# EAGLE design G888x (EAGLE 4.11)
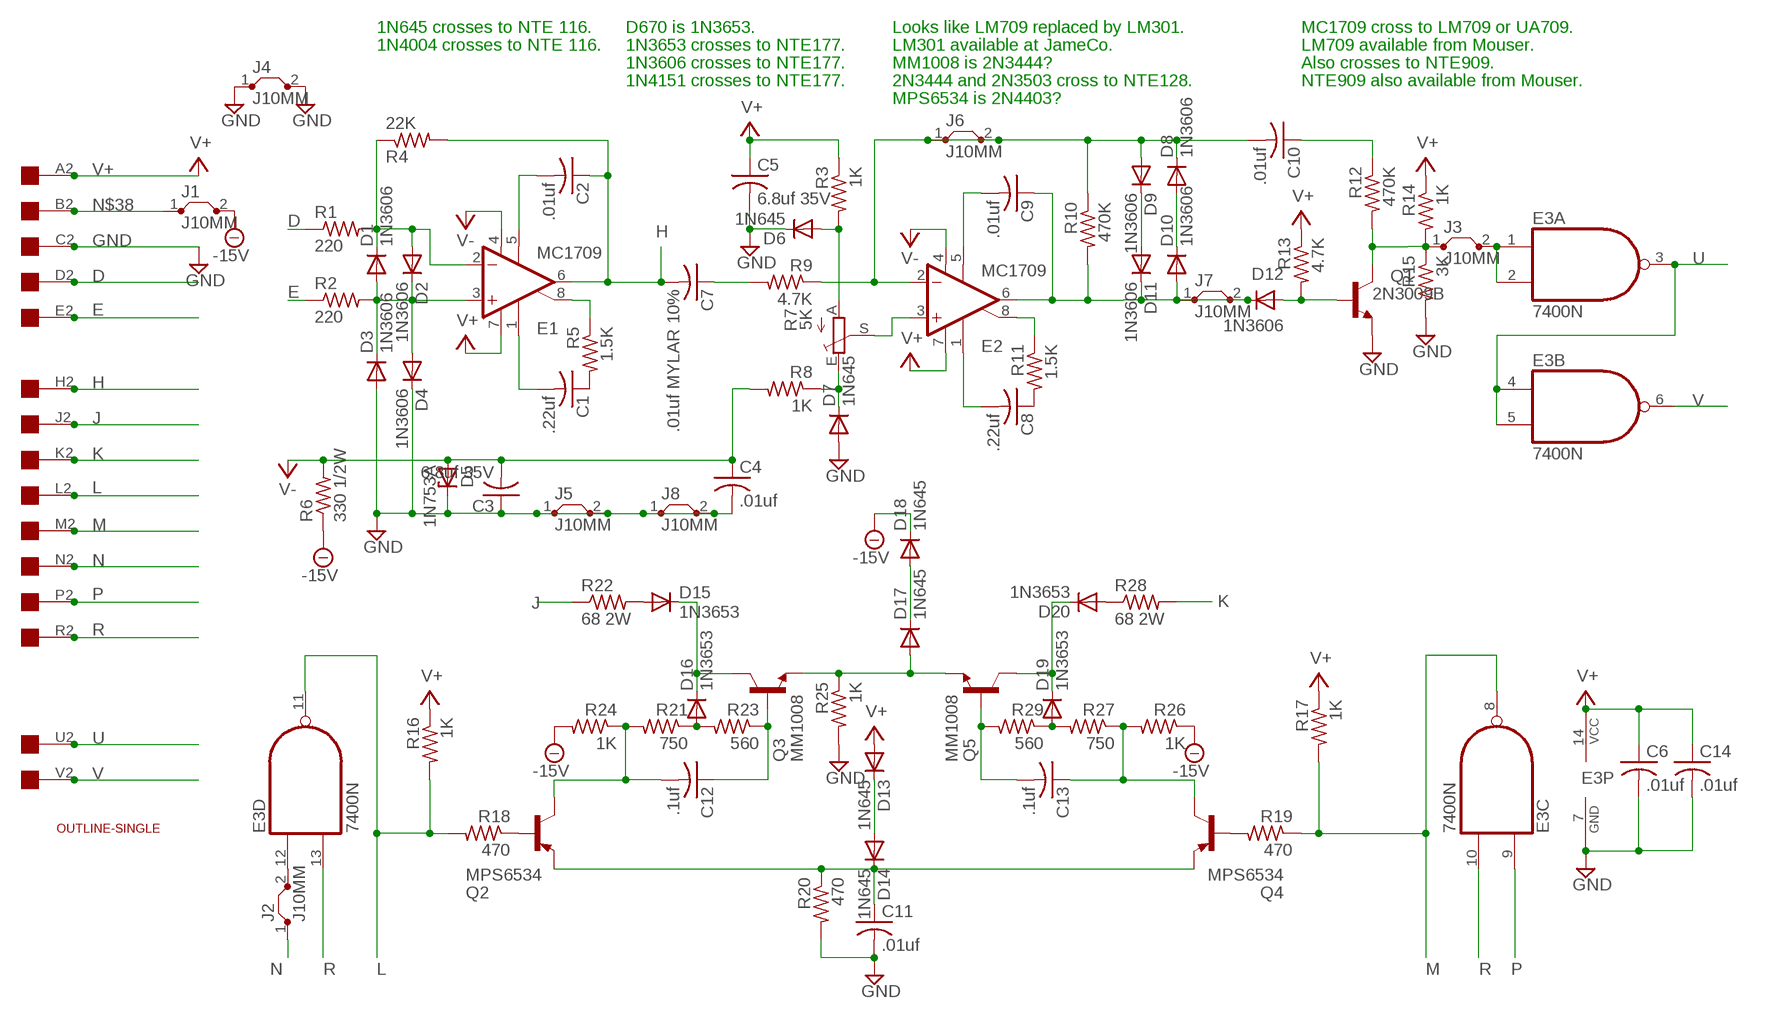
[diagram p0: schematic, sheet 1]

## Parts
C1  .22uf  C-US050-025X075  [C050-025X075]
C2  .01uf  C-US050-025X075  [C050-025X075]
C3  6.8uf 35V  C-US102-043X133  [C102-043X133]
C4  .01uf  C-US050-025X075  [C050-025X075]
C5  6.8uf 35V  C-US102-043X133  [C102-043X133]
C6  .01uf  C-US050-025X075  [C050-025X075]
C7  .01uf MYLAR 10%  C-US150-054X183  [C150-054X183]
C8  .22uf  C-US050-025X075  [C050-025X075]
C9  .01uf  C-US050-025X075  [C050-025X075]
C10  .01uf  C-US050-025X075  [C050-025X075]
C11  .01uf  C-US050-025X075  [C050-025X075]
C12  .1uf  C-US050-025X075  [C050-025X075]
C13  .1uf  C-US050-025X075  [C050-025X075]
C14  .01uf  C-US050-025X075  [C050-025X075]
D1  1N3606  1N4004  [DO41-10]
D2  1N3606  1N4004  [DO41-10]
D3  1N3606  1N4004  [DO41-10]
D4  1N3606  1N4004  [DO41-10]
D5  1N753A  ZENER-DIODEDO35Z10  [DO35Z10]
D6  1N645  1N4004  [DO41-10]
D7  1N645  1N4004  [DO41-10]
D8  1N3606  1N4004  [DO41-10]
D9  1N3606  1N4004  [DO41-10]
D10  1N3606  1N4004  [DO41-10]
D11  1N3606  1N4004  [DO41-10]
D12  1N3606  1N4004  [DO41-10]
D13  1N645  1N4004  [DO41-10]
D14  1N645  1N4004  [DO41-10]
D15  1N3653  1N4004  [DO41-10]
D16  1N3653  1N4004  [DO41-10]
D17  1N645  1N4004  [DO41-10]
D18  1N645  1N4004  [DO41-10]
D19  1N3653  1N4004  [DO41-10]
D20  1N3653  1N4004  [DO41-10]
E1  MC1709  LM3080N  [DIL08]
E2  MC1709  LM3080N  [DIL08]
E3  7400N  [DIL14]
J1  J10MM  [10]
J2  J10MM  [10]
J3  J10MM  [10]
J4  J10MM  [10]
J5  J10MM  [10]
J6  J10MM  [10]
J7  J10MM  [10]
J8  J10MM  [10]
Q1  2N3009B  2N1711  [TO39]
Q2  MPS6534  2N5415  [TO39]
Q3  MM1008  2N1711  [TO39]
Q4  MPS6534  2N5415  [TO39]
Q5  MM1008  2N1711  [TO39]
R1  220  R-US_0207/10  [0207/10]
R2  220  R-US_0207/10  [0207/10]
R3  1K  R-US_0207/10  [0207/10]
R4  22K  R-US_0207/10  [0207/10]
R5  1.5K  R-US_0207/10  [0207/10]
R6  330 1/2W  R-US_0411/15  [0411/15]
R7  5K  TRIM_EU-PTSPIN  [PT-SPIN]
R8  1K  R-US_0207/10  [0207/10]
R9  4.7K  R-US_0207/10  [0207/10]
R10  470K  R-US_0207/10  [0207/10]
R11  1.5K  R-US_0207/10  [0207/10]
R12  470K  R-US_0207/10  [0207/10]
R13  4.7K  R-US_0207/10  [0207/10]
R14  1K  R-US_0207/10  [0207/10]
R15  3K  R-US_0207/10  [0207/10]
R16  1K  R-US_0207/10  [0207/10]
R17  1K  R-US_0207/10  [0207/10]
R18  470  R-US_0207/10  [0207/10]
R19  470  R-US_0207/10  [0207/10]
R20  470  R-US_0207/10  [0207/10]
R21  750  R-US_0207/10  [0207/10]
R22  68 2W  R-US_0817/22  [P0817/22]
R23  560  R-US_0207/10  [0207/10]
R24  1K  R-US_0207/10  [0207/10]
R25  1K  R-US_0207/10  [0207/10]
R26  1K  R-US_0207/10  [0207/10]
R27  750  R-US_0207/10  [0207/10]
R28  68 2W  R-US_0817/22  [P0817/22]
R29  560  R-US_0207/10  [0207/10]
U$1  EDGE-1  [EDGE-CON1]
U$4  OUTLINE-SINGLE  [SINGLE]

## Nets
-15V: D18.C J1.2 R6.1 R24.2 R26.1
D: R1.1 U$1.D2
E: R2.1 U$1.E2
GND: C3.1 C4.2 C5.2 C6.2 C11.2 C14.2 D3.A D4.C D5.C D6.C D7.A E3.7(P:GND) J4.1 J4.2 J5.1 J5.2 J8.1 J8.2 Q1.1(E) R15.2 R20.2 R25.2 U$1.C2
H: C2.1 C7.2 E1.6(OUT) R4.2 U$1.H2
J: R22.1 U$1.J2
K: R28.2 U$1.K2
L: E3.11(D:O) R16.2 R18.2 U$1.L2
M: E3.8(C:O) R17.2 R19.1 U$1.M2
N: J2.1 U$1.N2
N$1: C1.1 R5.2
N$2: C8.1 R11.2
N$3: D1.C D2.A E1.2(-IN) R1.2 R4.1
N$4: D1.A D2.C D3.C D4.A E1.3(+IN) R2.2
N$5: C8.2 E2.1(ON1)
N$6: C1.2 E1.1(ON1)
N$7: E1.8(ON2) R5.1
N$8: C2.2 E1.5(OPT)
N$9: D6.A R3.2 R7.A
N$10: C10.2 D8.C D9.A E2.2(-IN) J6.1 J6.2 R9.1 R10.1
N$11: E2.3(+IN) R7.S
N$12: D7.C R7.E R8.1
N$13: E2.8(ON2) R11.1
N$14: C9.2 E2.5(OPT)
N$15: C9.1 D10.A D11.C D12.C E2.6(OUT) J7.1 J7.2 R10.2
N$16: C7.1 R9.2
N$17: D9.C D11.A
N$18: D8.A D10.C
N$19: C10.1 R12.1
N$20: D12.A Q1.2(B) R13.2
N$21: J3.1 Q1.3(C) R12.2 R14.2 R15.1
N$22: D17.A Q3.1(E) Q5.1(E) R25.1
N$23: C11.1 D14.C Q2.1(E) Q4.1(E) R20.1
N$24: D13.C D14.A
N$25: Q2.2(B) R18.1
N$26: Q4.2(B) R19.2
N$27: D15.A R22.2
N$28: D16.A R21.1 R23.2
N$29: C12.2 Q2.3(C) R21.2 R24.1
N$30: C12.1 Q3.2(B) R23.1
N$31: D19.A R27.2 R29.1
N$32: C13.1 Q4.3(C) R26.2 R27.1
N$33: C13.2 Q5.2(B) R29.2
N$34: D20.A R28.1
N$35: D15.C D16.C Q3.3(C)
N$36: D19.C D20.C Q5.3(C)
N$37: D17.C D18.A
N$38: J1.1 U$1.B2
N$39: E3.12(D:I0) J2.2
N$40: E3.1(A:I0) E3.2(A:I1) J3.2
P: E3.9(C:I0) U$1.P2
R: E3.10(C:I1) E3.13(D:I1) U$1.R2
U: E3.3(A:O) E3.4(B:I0) E3.5(B:I1) U$1.U2
V: E3.6(B:O) U$1.V2
V+: C5.1 C6.1 C14.1 D13.A E1.7(V+) E2.7(V+) E3.14(P:VCC) R3.1 R13.1 R14.1 R16.1 R17.1 U$1.A2
V-: C3.2 C4.1 D5.A E1.4(V-) E2.4(V-) R6.2 R8.2
Unconnected: U$1.F2 U$1.S2 U$1.T2

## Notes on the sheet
- 1N645 crosses to NTE 116. | D670 is 1N3653. | Looks like LM709 replaced by LM301. | MC1709 cross to LM709 or UA709.
- 1N4004 crosses to NTE 116. | 1N3653 crosses to NTE177. | LM301 available at JameCo. | LM709 available from Mouser.
- 1N3606 crosses to NTE177. | MM1008 is 2N3444? | Also crosses to NTE909.
- 1N4151 crosses to NTE177. | 2N3444 and 2N3503 cross to NTE128. | NTE909 also available from Mouser.
- MPS6534 is 2N4403?

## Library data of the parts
C1-C14 = rcl:C-US: CAPACITOR, American symbol
D1-D4 D6-D20 = diode:1N4004: DIODE
D5 = diode:ZENER-DIODE: Z-Diode
E1 E2 = linear:*3080: OP AMP
E3 = 74xx-us:74*00: Quad 2-input NAND gate
J1-J8 = jumper:J: Bridge
Q1 Q3 Q5 = transistor-npn:2N1711: NPN Transistor
Q2 Q4 = transistor-pnp:2N5415*: PNP Transistror
R1-R6 R8-R29 = rcl:R-US_: RESISTOR, American symbol
R7 = pot:TRIM_EU-: POTENTIOMETER
U$1 = dec-con:EDGE-1: Single-Sided DEC Edge Connector -- (side 2)
U$4 = dec-con:OUTLINE-*: Board outlines for DEC boards.

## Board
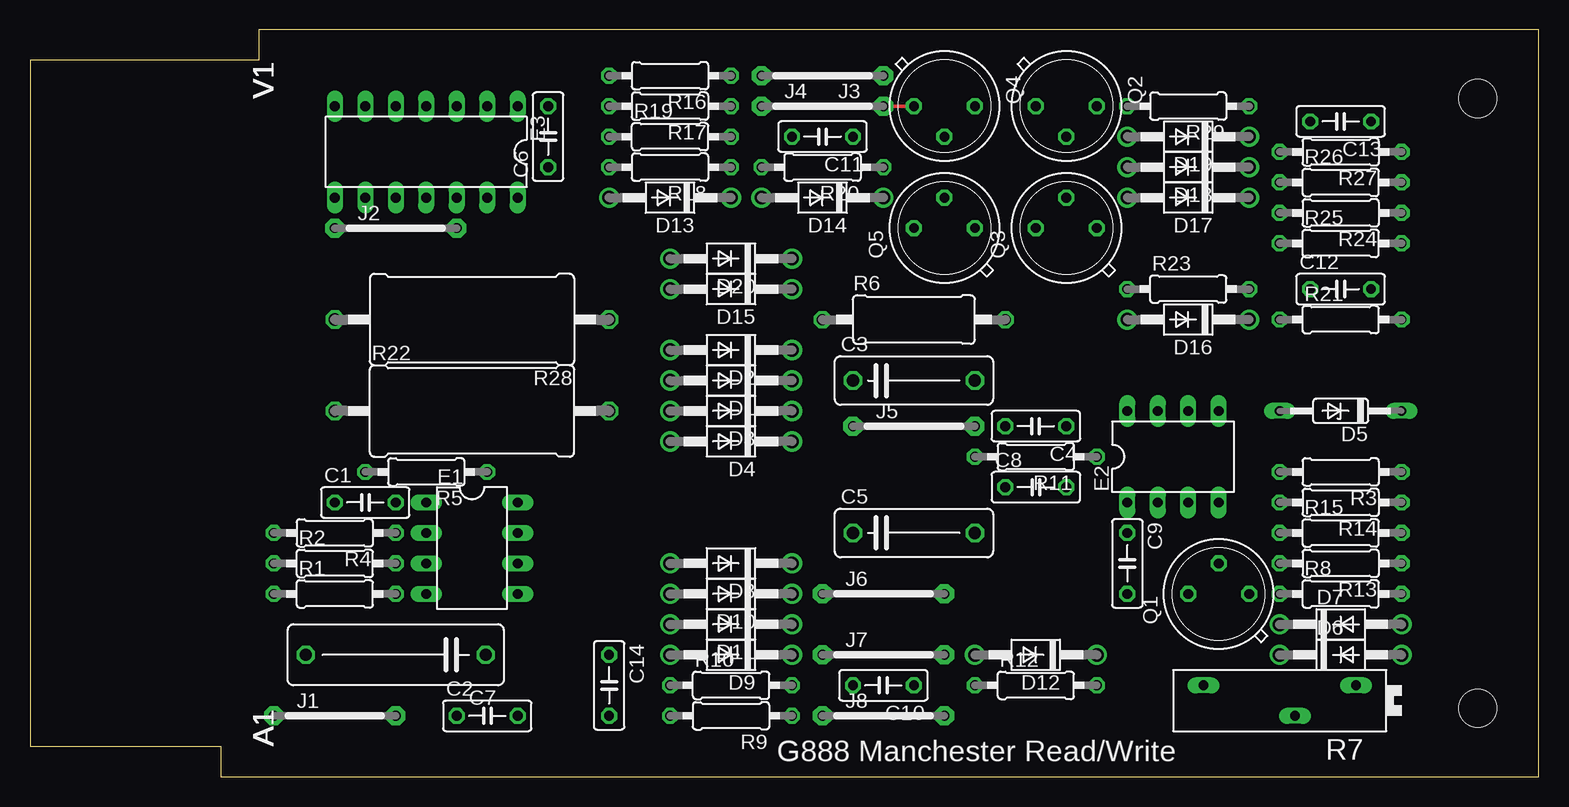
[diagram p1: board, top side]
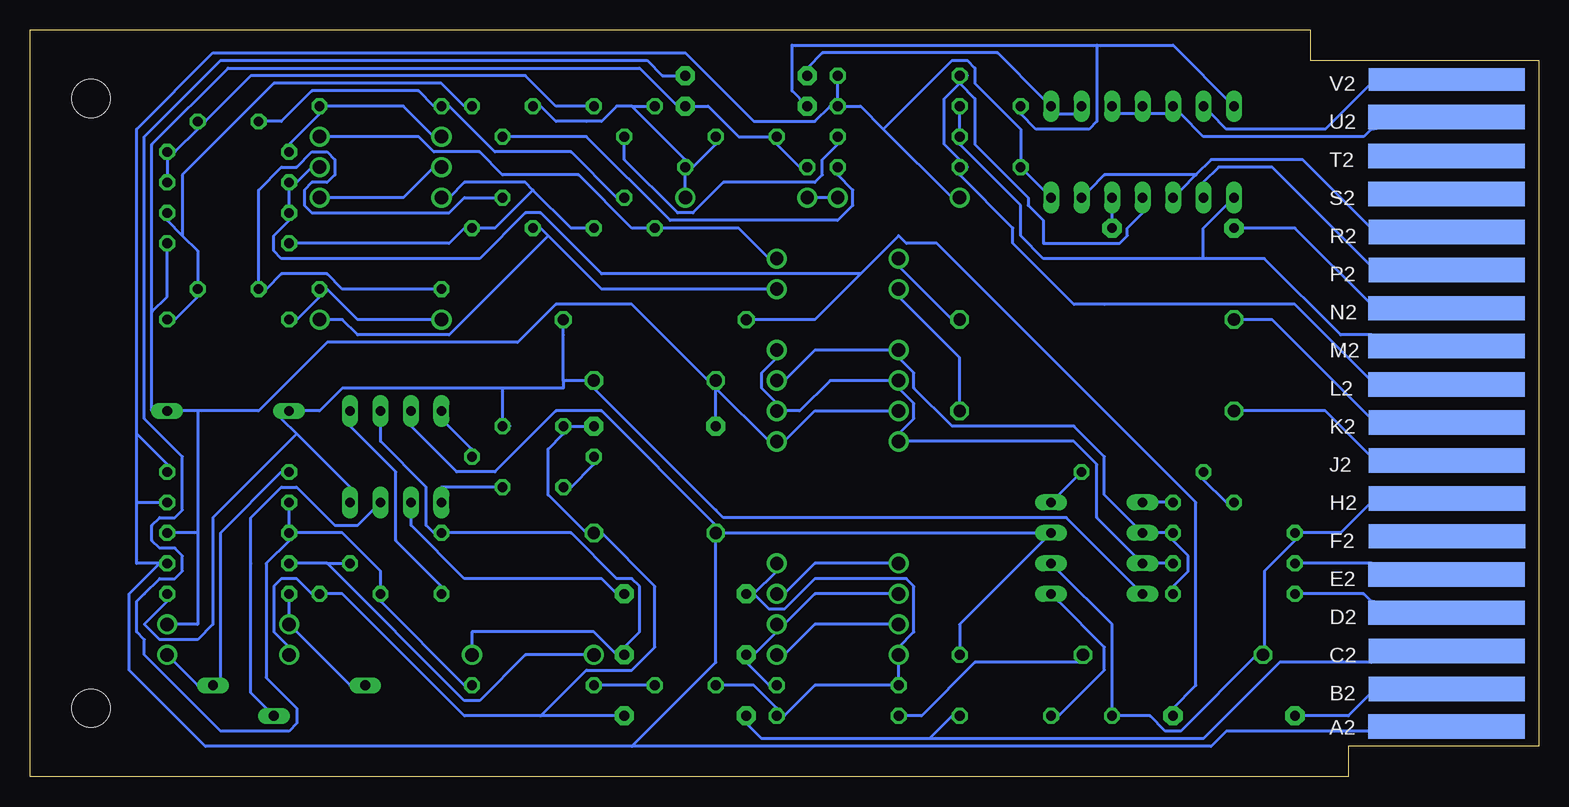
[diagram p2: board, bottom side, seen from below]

Size 125.73 x 62.23 mm. Coordinates in mm from the lower left corner, seen from the top.
Copper layers (1*16): Top 0.035mm / dielectric 1.5mm / Bottom 0.035mm
Design rules "custompcb": minimum track width 10mil, minimum drill 24mil, track to track 12mil, track to pad 12mil, pad to pad 12mil, via to via 12mil, smd to smd 12mil, copper to edge 25mil, drill to drill 12mil, minimum pad ring 10mil, minimum via ring 8mil, stop-mask expansion 0mil, vias tented up to drill 0mil, thermal gap 10mil

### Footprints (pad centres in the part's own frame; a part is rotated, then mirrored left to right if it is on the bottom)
C050-025X075 = drill 0.813 octagon: 1 -2.54,0; 2 2.54,0
C102-043X133 = drill 1.016 octagon: 1 -5.08,0; 2 5.08,0
C150-054X183 = drill 1.016 octagon: 1 -7.493,0; 2 7.493,0
DO41-10 = drill 1.118 round: A 5.08,0; C -5.08,0
DO35Z10 = drill 0.813 long: A 5.08,0; C -5.08,0
DIL08 = drill 0.813 long: 1 -3.81,-3.81; 2 -1.27,-3.81; 3 1.27,-3.81; 4 3.81,-3.81; 5 3.81,3.81; 6 1.27,3.81; 7 -1.27,3.81; 8 -3.81,3.81
DIL14 = drill 0.813 long: 1 -7.62,-3.81; 2 -5.08,-3.81; 3 -2.54,-3.81; 4 0,-3.81; 5 2.54,-3.81; 6 5.08,-3.81; 7 7.62,-3.81; 8 7.62,3.81; 9 5.08,3.81; 10 2.54,3.81; 11 0,3.81; 12 -2.54,3.81; 13 -5.08,3.81; 14 -7.62,3.81
10 = drill 0.813 pad 1.6 octagon: 1 -5.08,0; 2 5.08,0
TO39 = drill 0.813 octagon: 1 0,-2.54; 2 2.54,0; 3 0,2.54
0207/10 = drill 0.813 octagon: 1 -5.08,0; 2 5.08,0
0411/15 = drill 0.914 octagon: 1 -7.62,0; 2 7.62,0
PT-SPIN = drill 0.813 long: A -6.35,-1.27; E 6.35,-1.27; S -1.27,1.27
P0817/22 = drill 1.016 octagon: 1 -11.43,0; 2 11.43,0
EDGE-CON1 = smd 13.017 x 2.032 bottom: A2 7.69,4.194; B2 7.668,7.328; C2 7.668,10.49; D2 7.693,13.665; E2 7.693,16.84; F2 7.642,20.041; H2 7.642,23.19; J2 7.668,26.34; K2 7.668,29.515; L2 7.693,32.69; M2 7.693,35.89; N2 7.693,39.04; P2 7.668,42.24; R2 7.668,45.39; S2 7.693,48.565; T2 7.693,51.74; U2 7.693,54.966 | smd 13.017 x 1.905 bottom: V2 7.668,58.102
SINGLE = hole 3.175: 120.65,56.515; 120.65,5.715

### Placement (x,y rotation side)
C1  27.94,22.86 0 top
C2  38.1,5.08 0 top
C3  73.66,33.02 0 top
C4  83.82,29.21 180 top
C5  73.66,20.32 0 top
C6  43.18,53.34 90 top
C7  30.48,10.16 180 top
C8  83.82,24.13 0 top
C9  91.44,17.78 270 top
C10  71.12,7.62 180 top
C11  66.04,53.34 180 top
C12  109.22,40.64 0 top
C13  109.22,54.61 180 top
C14  48.26,7.62 270 top
D1  58.42,33.02 180 top
D2  58.42,35.56 180 top
D3  58.42,30.48 180 top
D4  58.42,27.94 180 top
D5  109.22,30.48 180 top
D6  109.22,10.16 0 top
D7  109.22,12.7 0 top
D8  58.42,17.78 180 top
D9  58.42,10.16 180 top
D10  58.42,15.24 180 top
D11  58.42,12.7 180 top
D12  83.82,10.16 180 top
D13  53.34,48.26 180 top
D14  66.04,48.26 180 top
D15  58.42,40.64 180 top
D16  96.52,38.1 180 top
D17  96.52,48.26 180 top
D18  96.52,50.8 180 top
D19  96.52,53.34 180 top
D20  58.42,43.18 180 top
E1  36.83,19.05 270 top
E2  95.25,26.67 0 top
E3  33.02,52.07 180 top
J1  25.4,5.08 0 top
J2  30.48,45.72 0 top
J3  66.04,58.42 180 top
J4  66.04,55.88 0 top
J5  73.66,29.21 0 top
J6  71.12,15.24 0 top
J7  71.12,10.16 0 top
J8  71.12,5.08 0 top
Q1  99.06,15.24 90 top
Q2  86.36,55.88 270 top
Q3  86.36,45.72 90 top
Q4  76.2,55.88 270 top
Q5  76.2,45.72 90 top
R1  25.4,15.24 0 top
R2  25.4,17.78 0 top
R3  109.22,25.4 180 top
R4  25.4,20.32 180 top
R5  33.02,25.4 180 top
R6  73.66,38.1 0 top
R7  104.14,6.35 180 top
R8  109.22,15.24 0 top
R9  58.42,5.08 180 top
R10  58.42,7.62 0 top
R11  83.82,26.67 180 top
R12  83.82,7.62 0 top
R13  109.22,17.78 180 top
R14  109.22,22.86 180 top
R15  109.22,20.32 0 top
R16  53.34,58.42 180 top
R17  53.34,55.88 180 top
R18  53.34,50.8 180 top
R19  53.34,53.34 0 top
R20  66.04,50.8 180 top
R21  109.22,38.1 0 top
R22  36.83,30.48 0 top
R23  96.52,40.64 0 top
R24  109.22,46.99 180 top
R25  109.22,44.45 0 top
R26  109.22,49.53 0 top
R27  109.22,52.07 180 top
R28  36.83,38.1 180 top
R29  96.52,55.88 180 top
U$1  0,0 0 top
U$4  0,0 0 top

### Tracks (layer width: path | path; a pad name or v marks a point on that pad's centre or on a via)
-15V
  Bottom 0.254: D18.C 102.24,50.8 103.51,49.53 R26.1 104.14,48.9 104.14,47.62 R24.2 104.14,46.35 105.41,45.09 105.41,43.81 104.78,43.18 88.27,43.18 84.46,46.99 83.19,46.99 78.11,41.91 56.52,41.91 | 56.52,41.91 53.98,44.45 53.34,45.09 52.71,44.45 50.17,44.45 28.58,22.86 28.58,7.62 30.48,5.71 J1.2 | 56.52,41.91 60.33,38.1 65.41,38.1 R6.1
D
  Bottom 0.254: 13.97,14.61 14.61,15.24 19.69,15.24 R1.1
  Bottom 0.305: U$1.D2 13.97,14.61
E
  Bottom 0.254: 13.97,17.78 19.69,17.78 R2.1
  Bottom 0.305: U$1.E2 13.97,17.78
GND
  Top 0.305: J4.1 J4.2 73.03,55.88 | J8.1 69.22,5.08
  Top 0.406: 69.22,5.08 J8.2 | J5.2 J5.1
  Bottom 0.254: D6.C 104.14,10.79 105.41,12.06 105.41,15.88 104.78,16.51 103.51,16.51 102.24,15.24 Q1.1 99.7,15.24 89.54,5.08 83.19,5.08 | 50.8,3.17 48.9,5.08 C14.2 | 50.8,3.17 64.77,3.17 66.04,4.45 J8.1 | 13.97,9.53 21.59,9.53 27.94,3.17 50.8,3.17 | J5.2 C4.2 81.28,28.57 82.55,27.3 82.55,23.5 79.38,20.32 C5.2 78.11,20.32 73.66,15.88 73.66,10.79 75.57,8.89 79.38,8.89 83.19,5.08 | J5.1 68.58,32.38 | 68.58,32.38 64.14,27.94 D4.C 62.87,27.94 60.33,30.48 D3.A | 68.58,32.38 C3.1 69.22,33.02 75.57,39.37 81.92,39.37 85.09,36.2 100.97,36.2 106.68,30.48 111.76,30.48 | 36.83,60.96 62.23,60.96 62.23,57.15 J4.1 | 36.83,60.96 30.48,60.96 E3.7 | 36.83,60.96 36.83,54.61 37.47,53.98 41.91,53.98 43.18,55.24 C6.2 | 115.57,38.73 114.3,40.01 R25.2 | 115.57,38.73 115.57,30.48 D5.C 111.76,30.48 | J8.2 83.19,5.08 | 115.57,38.73 115.57,52.7 109.22,59.05 74.93,59.05 71.76,55.88 J4.2 69.22,55.88 66.68,53.34 C11.2 63.5,52.7 61.6,50.8 R20.2 | 111.76,20.32 R15.2 | D7.A 111.76,12.7 111.76,20.32 | 111.76,30.48 111.76,20.32
  Bottom 0.305: U$1.C2 13.97,9.53
H
  Bottom 0.254: 13.97,22.86 16.51,20.32 19.69,20.32 R4.2 20.32,19.68 22.86,17.14 22.86,10.79 C7.2 23.5,10.16 29.85,3.81 31.12,3.81 32.39,5.08 34.93,5.08 C2.1 35.56,5.71 35.56,12.7 40.01,17.14 E1.6
  Bottom 0.305: U$1.H2 13.97,22.86
J
  Bottom 0.254: 13.97,26.67 17.78,30.48 24.77,30.48 R22.1
  Bottom 0.305: U$1.J2 13.97,26.67
K
  Bottom 0.254: 13.97,29.84 22.23,38.1 24.77,38.1 R28.2
  Bottom 0.305: U$1.K2 13.97,29.84
L
  Bottom 0.254: 48.26,57.78 49.53,56.52 49.53,52.7 48.26,51.44 R18.2 | 48.26,57.78 R16.2 | 13.97,33.02 20.32,39.37 36.2,39.37 38.74,39.37 43.82,44.45 43.82,45.72 48.26,50.16 R18.2 | E3.11 33.02,46.99 34.29,45.72 34.29,45.09 34.93,44.45 36.83,44.45 39.37,44.45 41.28,44.45 41.28,46.35 42.55,47.62 42.55,48.26 46.99,52.7 46.99,56.52 48.26,57.78 | R16.2 47.63,58.42 | R18.2 47.63,50.8 | 48.26,57.78 R16.2
  Bottom 0.305: U$1.L2 13.97,33.02
M
  Bottom 0.254: R19.1 48.26,53.98 48.26,55.24 R17.2 | 27.94,43.18 27.94,45.72 26.04,47.62 E3.8 | 27.94,43.18 38.74,43.18 41.28,43.18 43.18,45.09 43.18,47.62 48.26,52.7 | 48.26,52.7 R19.1 | 13.97,36.83 16.51,36.83 22.86,43.18 27.94,43.18 | 48.26,52.7 R19.1
  Bottom 0.305: U$1.M2 13.97,36.83 U$1.M2
N
  Bottom 0.254: 13.97,39.37 20.32,45.72 24.77,45.72 J2.1
  Bottom 0.305: U$1.N2 13.97,39.37
N$1
  Bottom 0.254: C1.1 26.04,22.86 27.94,24.77 R5.2
N$2
  Bottom 0.254: C8.1 80.65,24.13 78.74,26.04 R11.2
N$3
  Bottom 0.254: R1.2 30.48,15.88 29.21,17.14 29.21,18.41 30.48,19.68 R4.1 31.12,20.32 31.75,20.32 | 31.75,20.32 E1.2 | D1.C 62.87,33.02 60.33,35.56 53.98,35.56 D2.A 53.34,34.92 52.07,33.66 52.07,32.38 48.9,29.21 38.74,29.21 36.2,26.67 36.2,23.5 33.66,20.95 E1.2 | 31.75,20.32 E1.2
N$4
  Bottom 0.254: D2.C 63.5,34.92 64.77,33.66 64.77,32.38 63.5,31.11 D3.C 62.87,30.48 61.6,30.48 59.06,33.02 53.98,33.02 D1.A 53.34,32.38 52.07,31.11 52.07,29.84 53.34,28.57 D4.A 52.71,27.94 38.74,27.94 36.83,26.04 36.83,21.59 33.66,18.41 E1.3 31.75,17.78 31.12,17.78 R2.2
N$5
  Bottom 0.254: C8.2 87,24.13 91.44,24.13 E2.1
N$6
  Bottom 0.254: C1.2 31.12,22.86 31.75,22.86 E1.1
N$7
  Bottom 0.254: R5.1 40.01,23.5 E1.8
N$8
  Bottom 0.254: C2.2 40.01,5.08 36.2,8.89 36.2,10.79 40.01,14.61 E1.5
N$9
  Bottom 0.254: D6.A 111.76,7.62 R7.A 109.86,8.26 109.86,20.32 104.78,25.4 R3.2
N$10
  Top 0.406: J6.1 J6.2
  Bottom 0.254: 65.41,15.24 63.5,17.14 D8.C | 65.41,15.24 J6.1 65.41,15.24 | C10.2 67.95,7.62 65.41,7.62 63.5,5.71 R9.1 62.87,5.08 60.33,7.62 53.98,7.62 R10.1 53.34,8.26 53.34,9.53 D9.A 53.34,10.79 52.07,12.06 52.07,15.88 52.71,16.51 60.33,16.51 62.87,13.97 64.14,13.97 65.41,15.24 | E2.2 93.98,21.59 93.98,20.95 89.54,16.51 78.11,16.51 76.84,15.24 J6.2
N$11
  Bottom 0.254: R7.S 107.32,6.99 107.32,17.78 107.32,21.59 104.78,24.13 103.51,24.13 100.33,20.95 98.43,20.95 97.16,22.23 E2.3
N$12
  Bottom 0.254: R7.E 99.06,7.62 D7.C 104.14,13.34 104.14,14.61 R8.1
N$13
  Bottom 0.254: R11.1 88.9,27.3 91.44,29.84 E2.8
N$14
  Bottom 0.254: C9.2 91.44,15.88 95.25,19.68 95.25,25.4 99.06,29.21 E2.5
N$15
  Top 0.305: J7.1 69.22,10.16
  Top 0.406: 69.22,10.16 J7.2
  Bottom 0.254: D12.C 88.9,10.79 88.9,12.06 78.74,12.06 76.84,10.16 J7.2 76.2,10.79 74.93,12.06 74.93,15.88 75.57,16.51 76.84,16.51 80.65,20.32 90.81,20.32 C9.1 92.08,20.32 92.71,20.95 92.71,24.13 96.52,27.94 96.52,29.21 E2.6 | R10.2 64.14,7.62 66.04,9.53 J7.1 65.41,10.16 63.5,12.06 D11.C 62.87,12.7 60.33,15.24 53.98,15.24 D10.A
N$16
  Bottom 0.254: R9.2 52.71,5.08 51.44,5.08 46.99,9.53 38.1,9.53 C7.1
N$17
  Bottom 0.254: D11.A 53.98,12.7 60.33,12.7 62.87,10.16 D9.C
N$18
  Bottom 0.254: D8.A 53.98,17.78 60.33,17.78 62.87,15.24 D10.C
N$19
  Bottom 0.254: C10.1 74.3,7.62 78.11,7.62 R12.1
N$20
  Bottom 0.254: 100.97,17.78 99.7,17.78 Q1.2 | 100.97,17.78 103.51,17.78 R13.2 | 100.97,17.78 89.54,6.35 88.27,6.35 84.46,10.16 79.38,10.16 D12.A
N$21
  Top 0.406: J3.1 63.5,58.42
  Bottom 0.254: R15.1 104.14,20.95 104.14,22.23 R14.2 | R12.2 89.54,7.62 96.52,14.61 Q1.3 96.52,15.88 96.52,17.14 99.7,20.32 103.51,20.32 R15.1 | J3.1 71.76,58.42 73.03,58.42 74.3,59.69 109.86,59.69 116.21,53.34 116.21,29.84 113.03,26.67 113.03,22.23 113.67,21.59 114.94,21.59 115.57,20.95 115.57,19.68 114.94,19.05 113.67,19.05 113.03,18.41 113.03,17.14 113.67,16.51 114.94,16.51 116.21,15.24 116.84,14.61 116.84,12.06 116.21,11.43 116.21,10.16 109.86,3.81 104.14,3.81 103.51,4.45 103.51,5.71 106.05,8.26 106.05,17.78 104.14,19.68 R15.1
N$22
  Bottom 0.254: 83.82,48.9 84.46,49.53 89.54,49.53 90.81,48.26 D17.A | 83.82,48.9 80.65,45.72 79.38,45.72 Q5.1 | R25.1 103.51,44.45 90.81,44.45 89.54,45.72 Q3.1 88.27,45.72 87,45.72 83.82,48.9
N$23
  Bottom 0.254: R20.1 71.12,50.16 71.12,48.9 D14.C | C11.1 68.58,52.7 70.49,50.8 R20.1 | 75.57,55.88 74.3,55.88 Q4.1 | 75.57,55.88 76.84,55.88 78.11,54.61 79.38,54.61 81.92,54.61 83.19,55.88 Q2.1 | 75.57,55.88 71.12,51.44 R20.1
N$24
  Bottom 0.254: D13.C 59.06,48.26 60.33,48.26 D14.A
N$25
  Bottom 0.254: R18.1 58.42,50.16 57.15,48.9 57.15,47.62 58.42,46.35 72.39,46.35 79.38,53.34 85.73,53.34 Q2.2
N$26
  Bottom 0.254: R19.2 58.42,52.7 59.69,51.44 59.69,50.16 60.33,49.53 67.95,49.53 70.49,46.99 71.76,46.99 76.2,51.44 76.2,52.7 Q4.2
N$27
  Bottom 0.254: R22.2 48.26,31.11 48.26,34.92 53.34,40.01 D15.A
N$28
  Bottom 0.254: R21.1 103.51,38.1 101.6,40.01 R23.2 100.97,40.64 98.43,38.1 92.08,38.1 D16.A
N$29
  Bottom 0.254: R21.2 113.67,38.1 111.76,40.01 C12.2 111.76,41.27 111.76,43.81 113.03,45.09 | 113.03,45.09 114.3,46.35 R24.1 | 113.03,45.09 113.03,50.16 105.41,57.78 91.44,57.78 89.54,55.88 Q2.3
N$30
  Bottom 0.254: R23.1 92.08,40.64 99.7,40.64 100.97,41.91 104.78,41.91 106.05,40.64 C12.1 106.68,41.27 106.68,48.9 104.78,50.8 103.51,50.8 102.24,52.07 100.97,52.07 100.33,51.44 100.33,50.16 100.97,49.53 102.24,49.53 102.87,48.9 102.87,47.62 102.24,46.99 90.81,46.99 89.54,48.26 87,48.26 Q3.2
N$31
  Bottom 0.254: R27.2 104.14,52.7 101.6,55.24 R29.1 100.97,55.88 94.62,55.88 92.08,53.34 D19.A
N$32
  Bottom 0.254: R26.2 114.3,50.16 114.3,51.44 R27.1 113.67,52.07 111.76,53.98 C13.1 111.13,54.61 107.32,58.42 84.46,58.42 81.92,55.88 79.38,55.88 Q4.3
N$33
  Bottom 0.254: Q5.2 76.84,48.26 80.65,52.07 87,52.07 90.81,55.88 R29.2 92.08,55.88 93.35,57.15 102.24,57.15 104.78,54.61 106.05,54.61 C13.2
N$34
  Bottom 0.254: R28.1 48.9,38.1 53.34,42.55 D20.A
N$35
  Bottom 0.254: 82.55,45.09 78.11,40.64 64.14,40.64 D15.C | 82.55,45.09 83.19,45.72 Q3.3 | 82.55,45.09 90.81,36.83 98.43,36.83 99.7,38.1 100.97,38.1 D16.C
N$36
  Bottom 0.254: D20.C 64.14,43.18 66.68,45.72 73.03,45.72 Q5.3 74.3,45.72 75.57,45.72 80.01,50.16 86.36,50.16 88.27,52.07 92.08,52.07 93.35,53.34 100.97,53.34 D19.C
N$37
  Bottom 0.254: D17.C 100.97,48.26 94.62,48.26 92.08,50.8 D18.A
N$38
  Bottom 0.254: 13.97,6.99 15.88,5.08 19.69,5.08 J1.1
  Bottom 0.305: U$1.B2 13.97,6.99
N$39
  Bottom 0.254: E3.12 35.56,46.99 35.56,46.35 J2.2
N$40
  Bottom 0.254: E3.2 38.74,55.24 40.01,55.24 E3.1 41.28,56.52 45.09,60.33 59.69,60.33 60.96,59.05 J3.2
P
  Bottom 0.254: 13.97,42.55 22.23,50.8 26.67,50.8 27.94,49.53 E3.9
  Bottom 0.305: U$1.P2 13.97,42.55
R
  Bottom 0.254: 28.58,50.16 27.31,51.44 19.69,51.44 13.97,45.72 | 28.58,50.16 29.85,48.9 E3.10 | 28.58,50.16 36.2,50.16 37.47,48.9 E3.13
  Bottom 0.305: U$1.R2 13.97,45.72
U
  Bottom 0.254: E3.3 34.93,55.24 33.66,55.24 E3.4 32.39,55.24 31.12,55.24 E3.5 29.85,55.24 27.94,53.34 14.61,53.34 13.97,53.98
  Bottom 0.305: U$1.U2 13.97,53.98
V
  Bottom 0.254: 13.97,57.78 17.78,53.98 26.04,53.98 27.31,55.24 E3.6
  Bottom 0.305: U$1.V2 13.97,57.78
V+
  Bottom 0.254: C14.1 48.26,12.7 E1.7 C5.1 | R17.1 R16.1 | E3.14 C6.1 43.18,53.98 46.99,57.78 46.99,59.05 47.63,59.69 48.9,59.69 54.61,53.98 | 54.61,53.98 48.9,48.26 D13.A | 54.61,53.98 56.52,55.88 R17.1 | 116.84,28.57 116.84,53.98 110.49,60.33 71.12,60.33 65.41,54.61 60.33,54.61 59.06,55.88 R17.1 | 116.84,28.57 114.3,26.04 R3.1 | 116.84,22.86 116.84,28.57 | 116.84,22.86 116.84,17.78 114.94,17.78 | 116.84,22.86 R14.1 | 13.97,3.81 26.04,3.81 27.31,2.54 75.57,2.54 | 75.57,2.54 111.13,2.54 116.84,8.26 117.48,8.89 117.48,15.24 114.94,17.78 | 75.57,2.54 68.58,9.53 C5.1 | E2.7 93.98,29.21 90.17,25.4 87,25.4 81.92,30.48 78.11,30.48 68.58,20.95 C5.1 | 114.94,17.78 R13.1 114.94,17.78
  Bottom 0.305: U$1.A2 13.97,3.81
V-
  Bottom 0.254: 85.73,29.21 C4.1 86.36,29.84 86.36,32.38 | C3.2 79.38,33.02 | 81.28,33.02 81.28,32.38 86.36,32.38 | 81.28,33.02 81.28,36.83 81.28,37.47 R6.2 | E1.4 33.66,15.88 39.37,21.59 41.91,21.59 67.95,21.59 68.58,22.23 78.74,32.38 C3.2 | 103.51,28.57 104.78,29.84 D5.A 102.87,30.48 101.6,30.48 99.7,32.38 86.36,32.38 | 103.51,28.57 99.06,24.13 E2.4 | 79.38,33.02 81.28,33.02 | C3.2 79.38,33.02 | 103.51,28.57 110.49,21.59 110.49,12.7 111.76,11.43 114.94,11.43 115.57,12.06 116.21,12.7 115.57,13.34 114.3,14.61 R8.2

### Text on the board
tPlace: G888 Manchester Read/Write
tNames: V1 | V1 | V1 | V1 | V1 | V1 | V1 | V1 | V1 | V1 | V1 | V1 | V1 | V1 | V1 | V1 | V1 | V1 | V1 | V1 | V1 | V1 | V1 | V1 | V1 | V1 | V1 | V1 | V1 | V1 | V1 | V1 | A1 | A1 | A1 | A1 | A1 | A1 | A1 | A1 | A1 | A1 | A1 | A1 | A1 | A1 | A1 | A1 | A1 | A1 | A1 | A1 | A1 | A1 | A1 | A1 | A1 | A1 | A1 | A1 | A1 | A1 | A1 | A1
